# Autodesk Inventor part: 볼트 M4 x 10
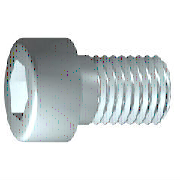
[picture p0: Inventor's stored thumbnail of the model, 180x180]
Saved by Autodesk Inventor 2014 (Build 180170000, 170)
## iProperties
IsCustomPart: 1
Created: 2012-02
Part Number: 볼트 M4 x 10
Material: 스테인리스강
Description: 6각 소켓 머리 캡 나사
Document SubType Name: Modeling
Standard: ISO 4762
Designer: mduedu
Standard Revision: Fourth edition 2004-03-01
Standards Organization: ISO
Language: ko-KR
Size Designation: M4 x 8
Categories: <MemberInstance><Categories><Category DisplayName="조임쇠" InternalName="e4da775c-781d-43d5-af7c-5136215cf5a6" Mnemonic="FSTN"><Category DisplayName="볼트" InternalN
Density: 7.75 g/cm^3
Appearance: 반광택
Author: mduedu
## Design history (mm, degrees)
sketch "스케치1"
  geometry: L1 (-1, 0)-(10, 0); L2 (10, 0)-(10, 2); L3 (10, 2)-(2.1, 2); L4 (2.1, 2)-(1.67, 2); L5 (1.67, 2)-(0, 2); L6 (0, 2)-(0, 3.5); L7 (0, 3.5)-(-4, 3.5); L8 (-4, 3.5)-(-4, 1.732); L9 (-4, 1.732)-(-2, 1.732); L10 (-2, 1.732)-(-1, 0); L11 (-6.8, 0)-(12.8, 0) reference; L12 (0, -0.7)-(0, 4.2) reference; L13 (2.1, 2)-(0, 2)
  constraints: 22 end point, 6 parallel, 2 collinear, 2 perpendicular, 1 horizontal, 1 point on line
  dimensions: "d1" = 7.9 distance from line of L3.end L2 (= GEL); "d2" = 0.42952 distance of L4.end L3.end (computed from GAL); "d3" = 4 distance between parallel lines of L8 L6 (= KOH); "d4" = 2 distance of L8.end L9.end (= INTI); "d5" = 60 deg angle of L10 L1; "d6" = 4 diameter of L3 L1 (= GD); "d7" = 4 diameter of L5 L1 (= BDM); "d8" = 3.4641 diameter of L9 L1 (= 1.1547 x SW); "d9" = 7 diameter of L7 L1 (= KOD); "d26" = 10 distance between parallel lines of L12 L2 (= NLG)
revolve "본체" sketch "스케치1" stored, may be unused: angle "d10" = 90 deg
sketch "스케치2"
  geometry: L1 (0, -4.9)-(0, 4.9) reference; L2 (-4.9, 0)-(4.9, 0) reference; L3 (1.732, 0)-(0.866, -1.5); L4 (0.866, -1.5)-(-0.866, -1.5); L5 (-0.866, -1.5)-(-1.732, 0); L6 (-1.732, 0)-(-0.866, 1.5); L7 (-0.866, 1.5)-(0.866, 1.5); L8 (0.866, 1.5)-(1.732, 0); 2 further points
  constraints: 12 end point, 1 coincident, 1 horizontal alignment, 1 point on line, 12 other
extrude "슬롯" join sketch "스케치2" stored distance "d11" = 10; taper "d12" = 0 deg
workplane "Work Plane1"
fillet "Fillet2" dims "d30" = 0.1 (= R)
body "Solid1"
fillet "모깎기1" dims "d17" = 0.4 (= RR)
feature "스레드" dims "d13" = 7.9 (= GEL), "d14" = 0
chamfer "모따기1" distance "d15" = 0.42941 (= -0.5 x SPD + 0.5 x GD); stored, may be unused: second distance "d16" = 0.42941 (= GUL), angle "d27" = 45 deg
other parameters: "GD" = 4 [user parameter; used in 2 equation terms], "NLG" = 10 [user parameter; used in 1 equation term], "GEL" = 7.9 [user parameter; used in 2 equation terms], "KOD" = 7 [user parameter; used in 1 equation term], "KOH" = 4 [user parameter; used in 1 equation term], "INTI" = 2 [user parameter; used in 1 equation term], "GAL" = 0.42941 (= 0.61345 x PTC) [user parameter; used in 1 equation term], "GUL" = 0.42941 (= 0.61345 x PTC) [user parameter; used in 1 equation term], "BDM" = 4 (= NND) [user parameter; used in 1 equation term], "SW" = 3 [user parameter; used in 2 equation terms], "RR" = 0.4 [user parameter; used in 1 equation term], "SPD" = 3.14117 (= NND - 1.2269 x PTC) [user parameter; used in 1 equation term], "d19" = 0, "d28" = 0, "d29" = 0, "R" = 0.1 [user parameter; used in 1 equation term], "TOA" = 30 deg [user parameter], "GD1" = 3.14117 (= THREADDIA - 1.2269 x PTC) [user parameter], "THREADDIA" = 4 [user parameter; used in 1 equation term], "FAWI" = 45 deg [user parameter], "TPU" = 14.28571 (computed from PTC) [user parameter], "PTC" = 0.7 [user parameter; used in 5 equation terms], "NND" = 4 [user parameter; used in 2 equation terms], "E0" = 3.465 (= 1.155 x SW) [user parameter]
